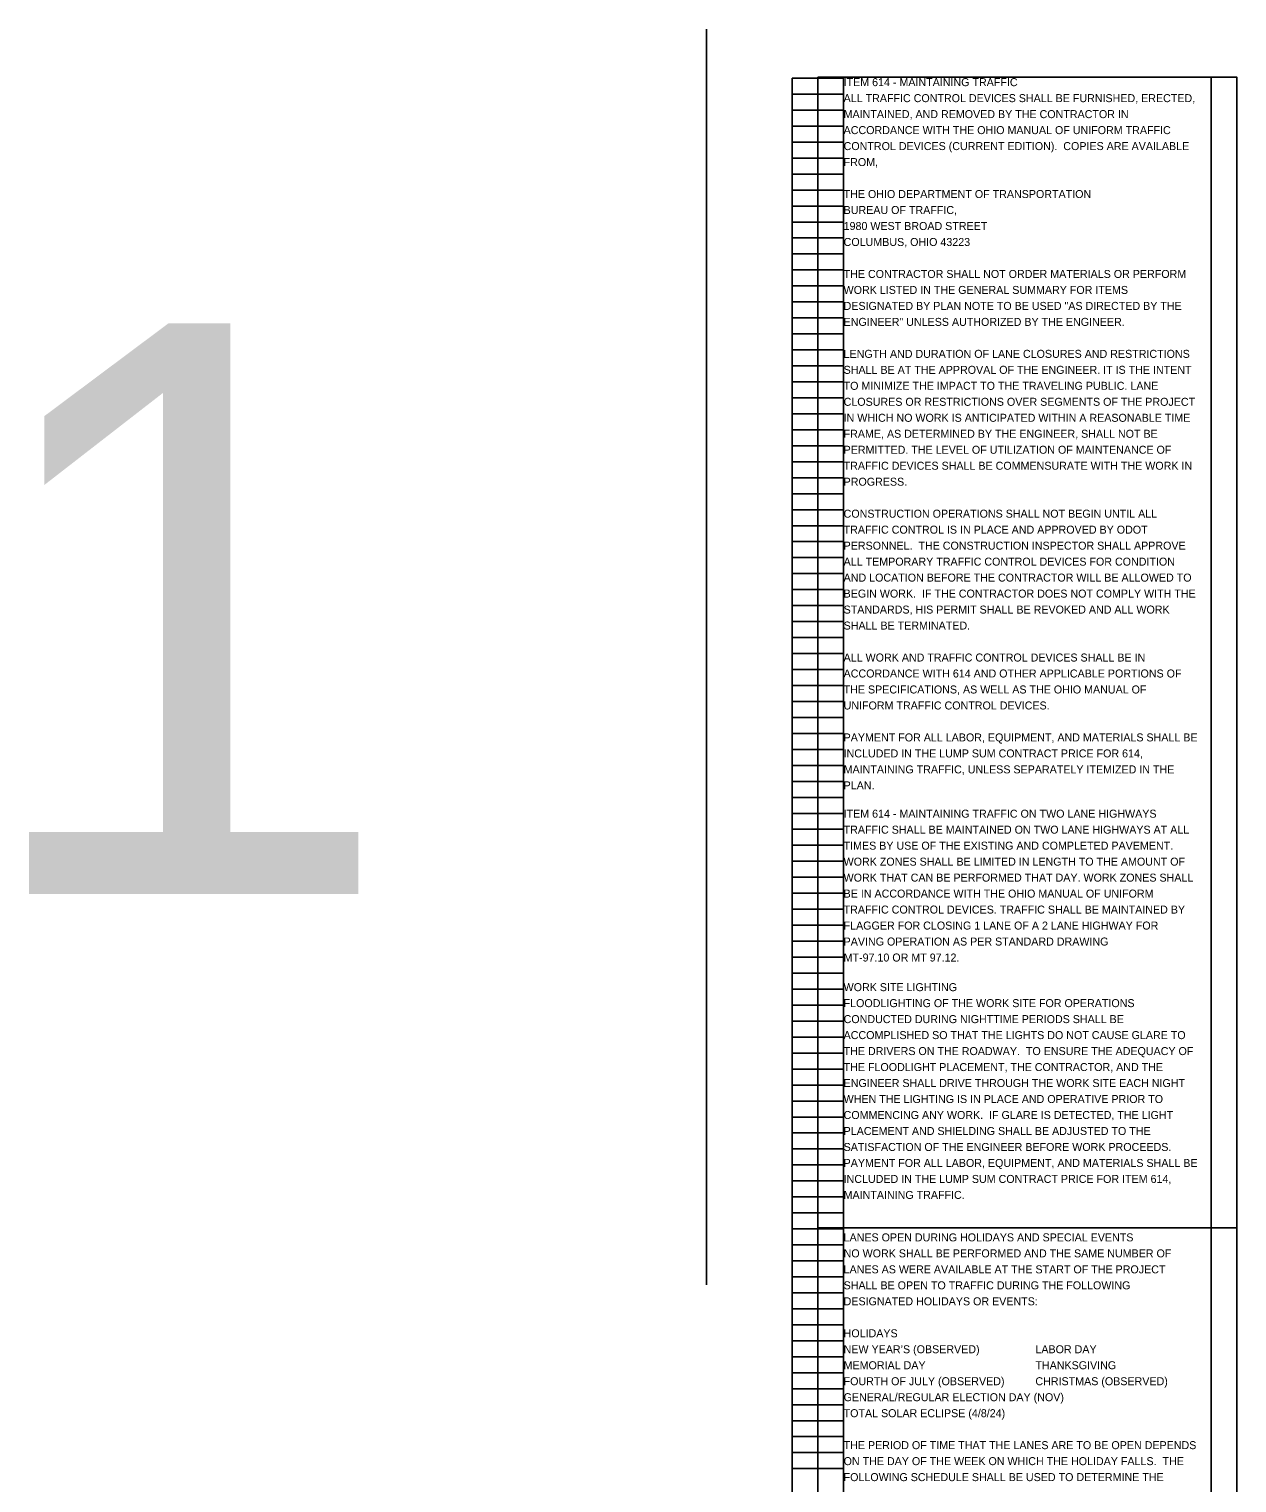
# Model space of a CAD drawing. Extents: x -13 to 29, y -301 to 22.
# Drawn here: x -11.87 to 9.29, y -3.47 to 22 of the extents above; entities that cross this region are included whole.
import ezdxf

# ---------------------------------------------------------------- set-up
doc = ezdxf.new("R2010")
doc.units = 0
doc.layers.add('SC_Scratch1', color=7, linetype='Continuous')
doc.layers.add('SH_Text', color=7, linetype='Continuous')

msp = doc.modelspace()

# ---------------------------------------------------------------- linework, layer by layer
at = {"layer": 'SH_Text'}
for p, q in [((0, 22), (0, 0)), ((1.5, 21.14), (2.4, 21.14)), ((1.5, 0.98), (1.5, 21.14)), ((2.4, 0.98), (2.4, 21.14)), ((8.84, 0.98), (8.84, 21.14)), ((1.5, 20.86), (2.4, 20.86)), ((1.5, 20.58), (2.4, 20.58)), ((1.5, 20.3), (2.4, 20.3)), ((1.5, 20.02), (2.4, 20.02)), ((1.5, 19.74), (2.4, 19.74)), ((1.5, 19.46), (2.4, 19.46)), ((1.5, 19.18), (2.4, 19.18)), ((1.5, 18.9), (2.4, 18.9)), ((1.5, 18.62), (2.4, 18.62)), ((1.5, 18.34), (2.4, 18.34)), ((1.5, 18.06), (2.4, 18.06)), ((1.5, 17.78), (2.4, 17.78)), ((1.5, 17.5), (2.4, 17.5)), ((1.5, 17.22), (2.4, 17.22)), ((1.5, 16.94), (2.4, 16.94)), ((1.5, 16.66), (2.4, 16.66)), ((1.5, 16.38), (2.4, 16.38)), ((1.5, 16.1), (2.4, 16.1)), ((1.5, 15.82), (2.4, 15.82)), ((1.5, 15.54), (2.4, 15.54)), ((1.5, 15.26), (2.4, 15.26)), ((1.5, 14.98), (2.4, 14.98)), ((1.5, 14.7), (2.4, 14.7)), ((1.5, 14.42), (2.4, 14.42)), ((1.5, 14.14), (2.4, 14.14)), ((1.5, 13.86), (2.4, 13.86)), ((1.5, 13.58), (2.4, 13.58)), ((1.5, 13.3), (2.4, 13.3)), ((1.5, 13.02), (2.4, 13.02)), ((1.5, 12.74), (2.4, 12.74)), ((1.5, 12.46), (2.4, 12.46)), ((1.5, 12.18), (2.4, 12.18)), ((1.5, 11.9), (2.4, 11.9)), ((1.5, 11.62), (2.4, 11.62)), ((1.5, 11.34), (2.4, 11.34)), ((1.5, 11.06), (2.4, 11.06)), ((1.5, 10.78), (2.4, 10.78)), ((1.5, 10.5), (2.4, 10.5)), ((1.5, 10.22), (2.4, 10.22)), ((1.5, 9.94), (2.4, 9.94)), ((1.5, 9.66), (2.4, 9.66)), ((1.5, 9.38), (2.4, 9.38)), ((1.5, 9.1), (2.4, 9.1)), ((1.5, 8.82), (2.4, 8.82)), ((1.5, 8.54), (2.4, 8.54)), ((1.5, 8.26), (2.4, 8.26)), ((1.5, 7.98), (2.4, 7.98)), ((1.5, 7.7), (2.4, 7.7)), ((1.5, 7.42), (2.4, 7.42)), ((1.5, 7.14), (2.4, 7.14)), ((1.5, 6.86), (2.4, 6.86)), ((1.5, 6.58), (2.4, 6.58)), ((1.5, 6.3), (2.4, 6.3)), ((1.5, 6.02), (2.4, 6.02)), ((1.5, 5.74), (2.4, 5.74)), ((1.5, 5.46), (2.4, 5.46)), ((1.5, 5.18), (2.4, 5.18)), ((1.5, 4.9), (2.4, 4.9)), ((1.5, 4.62), (2.4, 4.62)), ((1.5, 4.34), (2.4, 4.34)), ((1.5, 4.06), (2.4, 4.06)), ((1.5, 3.78), (2.4, 3.78)), ((1.5, 3.5), (2.4, 3.5)), ((1.5, 3.22), (2.4, 3.22)), ((1.5, 2.94), (2.4, 2.94)), ((1.5, 2.66), (2.4, 2.66)), ((1.5, 2.38), (2.4, 2.38)), ((1.5, 2.1), (2.4, 2.1)), ((1.5, 1.82), (2.4, 1.82)), ((1.5, 1.54), (2.4, 1.54)), ((1.5, 1.26), (2.4, 1.26)), ((1.5, 0.98), (2.4, 0.98)), ((1.5, 0.98), (2.4, 0.98)), ((1.5, -19.18), (1.5, 0.98)), ((2.4, -19.18), (2.4, 0.98)), ((8.84, -19.18), (8.84, 0.98)), ((1.5, 0.7), (2.4, 0.7)), ((1.5, 0.42), (2.4, 0.42)), ((1.5, 0.14), (2.4, 0.14)), ((1.5, -0.14), (2.4, -0.14)), ((1.5, -0.42), (2.4, -0.42)), ((1.5, -0.7), (2.4, -0.7)), ((1.5, -0.98), (2.4, -0.98)), ((1.5, -1.26), (2.4, -1.26)), ((1.5, -1.54), (2.4, -1.54)), ((1.5, -1.82), (2.4, -1.82)), ((1.5, -2.1), (2.4, -2.1)), ((1.5, -2.38), (2.4, -2.38)), ((1.5, -2.66), (2.4, -2.66)), ((1.5, -2.94), (2.4, -2.94)), ((1.5, -3.22), (2.4, -3.22))]:
    msp.add_line(p, q, dxfattribs=at)
for points in [[(1.95, 21.157), (9.29, 21.157), (9.29, 0.997), (1.95, 0.997)], [(1.95, 0.997), (9.29, 0.997), (9.29, -19.163), (1.95, -19.163)]]:
    msp.add_lwpolyline(points, close=True, dxfattribs=at)

# ---------------------------------------------------------------- texts
at = {"layer": 'SC_Scratch1'}
for s, height, p in [('ITEM 614 - MAINTAINING TRAFFIC', 0.14, (2.4, 21)), ('ALL TRAFFIC CONTROL DEVICES SHALL BE FURNISHED, ERECTED, ', 0.14, (2.4, 20.72)), ('MAINTAINED, AND REMOVED BY THE CONTRACTOR IN ', 0.14, (2.4, 20.44)), ('ACCORDANCE WITH THE OHIO MANUAL OF UNIFORM TRAFFIC ', 0.14, (2.4, 20.16)), ('CONTROL DEVICES (CURRENT EDITION).  COPIES ARE AVAILABLE ', 0.14, (2.4, 19.88)), ('FROM,', 0.14, (2.4, 19.6)), ('THE OHIO DEPARTMENT OF TRANSPORTATION', 0.14, (2.4, 19.04)), ('BUREAU OF TRAFFIC,', 0.14, (2.4, 18.76)), ('1980 WEST BROAD STREET', 0.14, (2.4, 18.48)), ('COLUMBUS, OHIO 43223 ', 0.14, (2.4, 18.2)), ('THE CONTRACTOR SHALL NOT ORDER MATERIALS OR PERFORM ', 0.14, (2.4, 17.64)), ('WORK LISTED IN THE GENERAL SUMMARY FOR ITEMS ', 0.14, (2.4, 17.36)), ('DESIGNATED BY PLAN NOTE TO BE USED "AS DIRECTED BY THE ', 0.14, (2.4, 17.08)), ('1', 10, (-12.888, 6.845)), ('ENGINEER" UNLESS AUTHORIZED BY THE ENGINEER.', 0.14, (2.4, 16.8)), ('LENGTH AND DURATION OF LANE CLOSURES AND RESTRICTIONS ', 0.14, (2.4, 16.24)), ('SHALL BE AT THE APPROVAL OF THE ENGINEER. IT IS THE INTENT ', 0.14, (2.4, 15.96)), ('TO MINIMIZE THE IMPACT TO THE TRAVELING PUBLIC. LANE ', 0.14, (2.4, 15.68)), ('CLOSURES OR RESTRICTIONS OVER SEGMENTS OF THE PROJECT ', 0.14, (2.4, 15.4)), ('IN WHICH NO WORK IS ANTICIPATED WITHIN A REASONABLE TIME ', 0.14, (2.4, 15.12)), ('FRAME, AS DETERMINED BY THE ENGINEER, SHALL NOT BE ', 0.14, (2.4, 14.84)), ('PERMITTED. THE LEVEL OF UTILIZATION OF MAINTENANCE OF ', 0.14, (2.4, 14.56)), ('TRAFFIC DEVICES SHALL BE COMMENSURATE WITH THE WORK IN ', 0.14, (2.4, 14.28)), ('PROGRESS.', 0.14, (2.4, 14)), ('CONSTRUCTION OPERATIONS SHALL NOT BEGIN UNTIL ALL ', 0.14, (2.4, 13.44)), ('TRAFFIC CONTROL IS IN PLACE AND APPROVED BY ODOT ', 0.14, (2.4, 13.16)), ('PERSONNEL.  THE CONSTRUCTION INSPECTOR SHALL APPROVE ', 0.14, (2.4, 12.88)), ('ALL TEMPORARY TRAFFIC CONTROL DEVICES FOR CONDITION ', 0.14, (2.4, 12.6)), ('AND LOCATION BEFORE THE CONTRACTOR WILL BE ALLOWED TO ', 0.14, (2.4, 12.32)), ('BEGIN WORK.  IF THE CONTRACTOR DOES NOT COMPLY WITH THE ', 0.14, (2.4, 12.04)), ('STANDARDS, HIS PERMIT SHALL BE REVOKED AND ALL WORK ', 0.14, (2.4, 11.76)), ('SHALL BE TERMINATED.', 0.14, (2.4, 11.48)), ('ALL WORK AND TRAFFIC CONTROL DEVICES SHALL BE IN ', 0.14, (2.4, 10.92)), ('ACCORDANCE WITH 614 AND OTHER APPLICABLE PORTIONS OF ', 0.14, (2.4, 10.64)), ('THE SPECIFICATIONS, AS WELL AS THE OHIO MANUAL OF ', 0.14, (2.4, 10.36)), ('UNIFORM TRAFFIC CONTROL DEVICES.  ', 0.14, (2.4, 10.08)), ('PAYMENT FOR ALL LABOR, EQUIPMENT, AND MATERIALS SHALL BE ', 0.14, (2.4, 9.52)), ('INCLUDED IN THE LUMP SUM CONTRACT PRICE FOR 614, ', 0.14, (2.4, 9.24)), ('MAINTAINING TRAFFIC, UNLESS SEPARATELY ITEMIZED IN THE ', 0.14, (2.4, 8.96)), ('PLAN.', 0.14, (2.4, 8.68)), ('ITEM 614 - MAINTAINING TRAFFIC ON TWO LANE HIGHWAYS', 0.14, (2.4, 8.184)), ('TRAFFIC SHALL BE MAINTAINED ON TWO LANE HIGHWAYS AT ALL ', 0.14, (2.4, 7.904)), ('TIMES BY USE OF THE EXISTING AND COMPLETED PAVEMENT.  ', 0.14, (2.4, 7.624)), ('WORK ZONES SHALL BE LIMITED IN LENGTH TO THE AMOUNT OF ', 0.14, (2.4, 7.344)), ('WORK THAT CAN BE PERFORMED THAT DAY. WORK ZONES SHALL ', 0.14, (2.4, 7.064)), ('BE IN ACCORDANCE WITH THE OHIO MANUAL OF UNIFORM ', 0.14, (2.4, 6.784)), ('TRAFFIC CONTROL DEVICES. TRAFFIC SHALL BE MAINTAINED BY ', 0.14, (2.4, 6.504)), ('FLAGGER FOR CLOSING 1 LANE OF A 2 LANE HIGHWAY FOR ', 0.14, (2.4, 6.224)), ('PAVING OPERATION AS PER STANDARD DRAWING', 0.14, (2.4, 5.944)), ('MT-97.10 OR MT 97.12.', 0.14, (2.4, 5.664)), ('WORK SITE LIGHTING', 0.14, (2.4, 5.145)), ('FLOODLIGHTING OF THE WORK SITE FOR OPERATIONS ', 0.14, (2.4, 4.865)), ('CONDUCTED DURING NIGHTTIME PERIODS SHALL BE ', 0.14, (2.4, 4.585)), ('ACCOMPLISHED SO THAT THE LIGHTS DO NOT CAUSE GLARE TO ', 0.14, (2.4, 4.305)), ('THE DRIVERS ON THE ROADWAY.  TO ENSURE THE ADEQUACY OF ', 0.14, (2.4, 4.025)), ('THE FLOODLIGHT PLACEMENT, THE CONTRACTOR, AND THE ', 0.14, (2.4, 3.745)), ('ENGINEER SHALL DRIVE THROUGH THE WORK SITE EACH NIGHT ', 0.14, (2.4, 3.465)), ('WHEN THE LIGHTING IS IN PLACE AND OPERATIVE PRIOR TO ', 0.14, (2.4, 3.185)), ('COMMENCING ANY WORK.  IF GLARE IS DETECTED, THE LIGHT ', 0.14, (2.4, 2.905)), ('PLACEMENT AND SHIELDING SHALL BE ADJUSTED TO THE ', 0.14, (2.4, 2.625)), ('SATISFACTION OF THE ENGINEER BEFORE WORK PROCEEDS.  ', 0.14, (2.4, 2.345)), ('PAYMENT FOR ALL LABOR, EQUIPMENT, AND MATERIALS SHALL BE ', 0.14, (2.4, 2.065)), ('INCLUDED IN THE LUMP SUM CONTRACT PRICE FOR ITEM 614, ', 0.14, (2.4, 1.785)), ('MAINTAINING TRAFFIC.', 0.14, (2.4, 1.505)), ('LANES OPEN DURING HOLIDAYS AND SPECIAL EVENTS', 0.14, (2.4, 0.761)), ('NO WORK SHALL BE PERFORMED AND THE SAME NUMBER OF ', 0.14, (2.4, 0.481)), ('LANES AS WERE AVAILABLE AT THE START OF THE PROJECT ', 0.14, (2.4, 0.201)), ('SHALL BE OPEN TO TRAFFIC DURING THE FOLLOWING ', 0.14, (2.4, -0.079)), ('DESIGNATED HOLIDAYS OR EVENTS:', 0.14, (2.4, -0.359)), ('HOLIDAYS', 0.14, (2.4, -0.919)), ('NEW YEAR’S (OBSERVED)', 0.14, (2.4, -1.199)), ('LABOR DAY', 0.14, (5.76, -1.199)), ('MEMORIAL DAY ', 0.14, (2.4, -1.479)), ('THANKSGIVING', 0.14, (5.76, -1.479)), ('FOURTH OF JULY (OBSERVED)', 0.14, (2.4, -1.759)), ('CHRISTMAS (OBSERVED)', 0.14, (5.76, -1.759)), ('GENERAL/REGULAR ELECTION DAY (NOV)', 0.14, (2.4, -2.039)), ('TOTAL SOLAR ECLIPSE (4/8/24)', 0.14, (2.4, -2.319)), ('THE PERIOD OF TIME THAT THE LANES ARE TO BE OPEN DEPENDS ', 0.14, (2.4, -2.879)), ('ON THE DAY OF THE WEEK ON WHICH THE HOLIDAY FALLS.  THE ', 0.14, (2.4, -3.159)), ('FOLLOWING SCHEDULE SHALL BE USED TO DETERMINE THE ', 0.14, (2.4, -3.439))]:
    msp.add_text(s, height=height, dxfattribs=at).set_placement(p)

doc.saveas('drawing.dxf')
